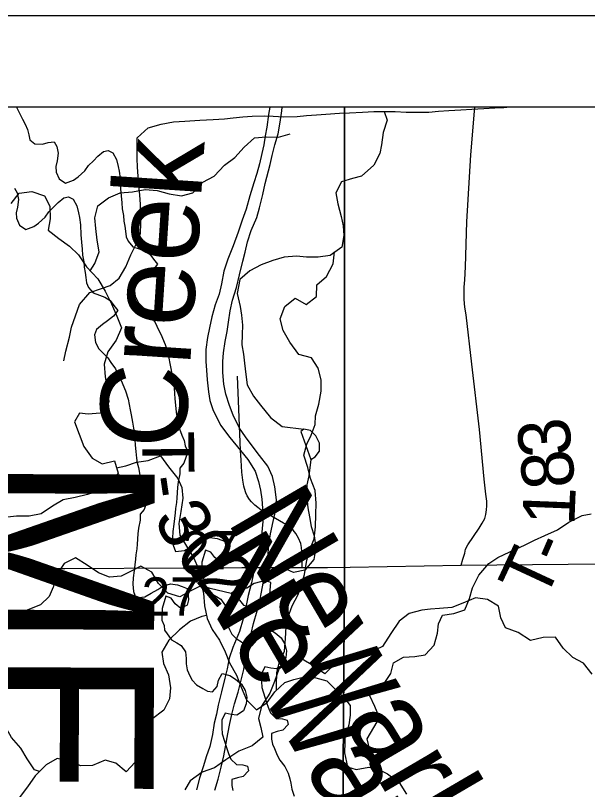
# Model space of a CAD drawing. Extents: x -21.1 to 50.3, y 0 to 22.1.
# Drawn here: x 6.171 to 6.795, y 20.155 to 21 of the extents above; entities that cross this region are included whole.
import ezdxf

# ---------------------------------------------------------------- set-up
doc = ezdxf.new("R2010")
doc.units = 0
for name, color, linetype in [('GM_X_County', 7, 'Continuous'), ('GM_X_County_Text', 7, 'Continuous'), ('GM_X_Minor_Lake', 7, 'Continuous'), ('GM_X_Minor_River', 7, 'Continuous'), ('GM_X_Minor_River_Text', 7, 'Continuous'), ('GM_X_Section_Text', 7, 'Continuous'), ('GM_X_State_Route', 7, 'Continuous'), ('GM_X_Township_Road', 7, 'Continuous'), ('GM_X_Township_Road_Text', 7, 'Continuous'), ('SH_Cut_Line', 7, 'Continuous'), ('SH_Data', 7, 'Continuous')]:
    doc.layers.add(name, color=color, linetype=linetype)

msp = doc.modelspace()

# ---------------------------------------------------------------- linework, layer by layer
at = {"layer": 'GM_X_County'}
msp.add_lwpolyline([(8.9, 14.74638), (8.9, 20.9), (2.1, 20.9), (2.1, 14.1), (8.89319, 14.1)], dxfattribs=at)
at = {"layer": 'GM_X_Minor_Lake'}
for points in [[(6.49289, 20.51509), (6.49782, 20.51812), (6.50237, 20.52419), (6.50238, 20.53291), (6.49821, 20.54088), (6.49253, 20.54694), (6.48533, 20.54808), (6.48191, 20.54581)], [(6.48191, 20.54581), (6.49289, 20.51509)], [(6.44922, 20.38083), (6.44354, 20.38272), (6.43785, 20.38158), (6.43103, 20.37969), (6.42307, 20.37475), (6.41662, 20.37399), (6.4098, 20.37134), (6.406, 20.36868), (6.40676, 20.36679), (6.41358, 20.36337), (6.41964, 20.35617), (6.42381, 20.35503), (6.4314, 20.35655), (6.43936, 20.35996), (6.44467, 20.36224), (6.4477, 20.36376)], [(6.4477, 20.36376), (6.44922, 20.38083)]]:
    msp.add_lwpolyline(points, dxfattribs=at)
at = {"layer": 'GM_X_Minor_River'}
for points in [[(6.17189, 20.9), (6.17446, 20.89495), (6.17831, 20.88661), (6.18138, 20.88131), (6.1837, 20.87563), (6.18526, 20.86955), (6.18643, 20.86424), (6.19178, 20.85971), (6.20016, 20.85938), (6.20624, 20.86131), (6.21271, 20.86211)], [(6.22342, 20.62276), (6.2257, 20.63338), (6.2295, 20.64855), (6.23178, 20.65955), (6.23596, 20.67207), (6.24051, 20.6842), (6.25189, 20.69748), (6.2644, 20.70203), (6.27389, 20.70506), (6.28374, 20.71303), (6.29095, 20.72555), (6.29665, 20.73844), (6.30348, 20.75247), (6.3069, 20.76233), (6.30728, 20.77258), (6.3069, 20.78395), (6.30691, 20.79343), (6.30616, 20.80405), (6.30541, 20.81391), (6.30465, 20.82453), (6.3039, 20.83439), (6.30353, 20.84387), (6.30354, 20.86625), (6.3153, 20.87725), (6.3297, 20.88142), (6.34297, 20.8837), (6.35548, 20.88446), (6.37178, 20.8856), (6.38619, 20.88636), (6.3987, 20.88712), (6.40818, 20.88826), (6.41879, 20.8894), (6.42903, 20.89016), (6.4423, 20.89054), (6.45177, 20.89016), (6.46352, 20.8894), (6.47793, 20.88978), (6.48816, 20.89092), (6.49916, 20.89168), (6.50939, 20.89206), (6.52418, 20.8932), (6.53517, 20.89358), (6.5492, 20.89434), (6.56171, 20.8951), (6.57308, 20.89511), (6.58483, 20.89511), (6.59696, 20.89435), (6.6216, 20.89435), (6.63222, 20.89549), (6.64359, 20.89625), (6.65648, 20.89701), (6.66861, 20.89777), (6.68188, 20.89853), (6.69363, 20.89929), (6.70348, 20.89967), (6.70676, 20.9)], [(6.44809, 20.9), (6.4468, 20.89182), (6.44476, 20.87817), (6.44315, 20.86869), (6.44153, 20.85883), (6.43953, 20.84935), (6.43676, 20.83798), (6.43399, 20.82737), (6.43085, 20.81715), (6.42653, 20.80314), (6.4222, 20.78836), (6.41791, 20.77663), (6.41359, 20.76338), (6.40813, 20.74862), (6.40228, 20.73387), (6.39797, 20.72061), (6.39555, 20.70696), (6.39277, 20.6956), (6.38848, 20.68386), (6.38493, 20.67098), (6.38253, 20.65885), (6.38014, 20.64824), (6.37849, 20.63534), (6.37835, 20.62205), (6.37902, 20.61254), (6.37967, 20.60228), (6.38143, 20.58897), (6.38285, 20.57946), (6.38616, 20.56955), (6.39434, 20.55275), (6.40445, 20.53897), (6.41607, 20.5248), (6.42432, 20.51522), (6.43216, 20.50222), (6.43584, 20.49117), (6.43802, 20.48165), (6.43944, 20.47176), (6.4401, 20.46188), (6.44074, 20.45085), (6.43988, 20.44023), (6.43902, 20.43074), (6.437, 20.41898), (6.43421, 20.40572), (6.43026, 20.39094), (6.42825, 20.38033), (6.42469, 20.36669), (6.4223, 20.35569), (6.41912, 20.34129), (6.41518, 20.32728), (6.40779, 20.30988), (6.40387, 20.29814), (6.40147, 20.28639), (6.39909, 20.27616), (6.39552, 20.26138), (6.39195, 20.24698), (6.38995, 20.23712), (6.38757, 20.22727), (6.38555, 20.21476), (6.38276, 20.20187), (6.37884, 20.19051), (6.37571, 20.18067), (6.37139, 20.16704), (6.36823, 20.15453)], [(6.38834, 20.15395), (6.39188, 20.16607), (6.39505, 20.17895), (6.39784, 20.19146), (6.39983, 20.20132), (6.40226, 20.21535), (6.40465, 20.22672), (6.40665, 20.23658), (6.40981, 20.24832), (6.41374, 20.26119), (6.41691, 20.27408), (6.41968, 20.28583), (6.42211, 20.30024), (6.42413, 20.31237), (6.42768, 20.32525), (6.43045, 20.33586), (6.43439, 20.34987), (6.43716, 20.36086), (6.43916, 20.37034), (6.44078, 20.3802), (6.44358, 20.39461), (6.446, 20.40788), (6.44728, 20.4223), (6.44892, 20.43406), (6.45172, 20.44733), (6.45449, 20.45869), (6.45538, 20.47122), (6.45363, 20.48529), (6.45109, 20.49671), (6.44589, 20.50778), (6.4369, 20.51965), (6.42903, 20.52999), (6.42154, 20.53994), (6.41519, 20.5495), (6.40812, 20.56363), (6.40405, 20.57392), (6.4, 20.5865), (6.39784, 20.59754), (6.39683, 20.61008), (6.39695, 20.62224), (6.39781, 20.63173), (6.39946, 20.64387), (6.40147, 20.65486), (6.40309, 20.6651), (6.40474, 20.67762), (6.40751, 20.68899), (6.41183, 20.703), (6.41501, 20.71664), (6.41858, 20.7318), (6.42134, 20.74165), (6.42373, 20.75264), (6.42766, 20.76514), (6.43388, 20.77951), (6.43702, 20.79011), (6.44059, 20.80451), (6.44299, 20.81665), (6.44852, 20.8371), (6.4509, 20.84696), (6.45367, 20.8587), (6.45722, 20.87082), (6.45962, 20.88333), (6.46127, 20.89585), (6.46179, 20.9)], [(6.57308, 20.89511), (6.57611, 20.88562), (6.57193, 20.87235), (6.57003, 20.8587), (6.56813, 20.84922), (6.56168, 20.8367), (6.5484, 20.82456), (6.53854, 20.82191), (6.52641, 20.81849), (6.52034, 20.80635), (6.52223, 20.79422), (6.52601, 20.78057), (6.52828, 20.77033), (6.52903, 20.75971), (6.52675, 20.74681), (6.51386, 20.73771), (6.50097, 20.73619), (6.48808, 20.73619), (6.47747, 20.73733), (6.46382, 20.73619), (6.45131, 20.73239), (6.43879, 20.72784), (6.42628, 20.72101), (6.41529, 20.71153), (6.41262, 20.69636), (6.41565, 20.68233), (6.41716, 20.67285), (6.41829, 20.66185), (6.4179, 20.65161), (6.41752, 20.64023), (6.41941, 20.62999), (6.42054, 20.62013), (6.42205, 20.608), (6.42356, 20.59662), (6.43038, 20.5841), (6.43796, 20.57462), (6.44894, 20.56097), (6.46183, 20.55111), (6.48533, 20.54808)], [(6.25213, 20.72115), (6.25709, 20.72899), (6.26202, 20.74193), (6.25972, 20.75447), (6.25817, 20.7674), (6.2574, 20.77919), (6.26042, 20.79213), (6.27221, 20.80089), (6.28475, 20.80623), (6.29845, 20.80739), (6.31214, 20.81007), (6.32508, 20.80895), (6.33841, 20.80516), (6.35173, 20.8029), (6.36428, 20.80634), (6.37492, 20.81814), (6.38746, 20.82462), (6.39886, 20.83643), (6.40988, 20.84481), (6.42014, 20.85624), (6.43154, 20.86652), (6.44409, 20.8673), (6.45779, 20.86694), (6.47034, 20.87075)], [(6.21271, 20.86211), (6.21578, 20.85681), (6.21734, 20.8496), (6.21625, 20.84123), (6.21476, 20.83515), (6.21518, 20.82907), (6.21826, 20.82149), (6.22514, 20.81697), (6.23388, 20.82005), (6.23918, 20.82388), (6.24638, 20.83038), (6.25016, 20.8361), (6.25584, 20.84145), (6.26038, 20.84642), (6.26682, 20.85139), (6.27176, 20.85256), (6.27673, 20.84992), (6.28095, 20.84273), (6.28252, 20.83514), (6.28369, 20.82983), (6.28488, 20.82186), (6.28532, 20.81084), (6.28612, 20.80287), (6.28655, 20.79527), (6.28697, 20.78882), (6.28853, 20.78161), (6.28894, 20.77553), (6.29012, 20.76984), (6.29053, 20.76452), (6.29132, 20.75845), (6.29363, 20.75352), (6.29862, 20.74747), (6.30548, 20.74523), (6.31158, 20.74298), (6.31732, 20.73922), (6.32115, 20.73392), (6.32575, 20.72825), (6.32084, 20.72214), (6.31439, 20.71717), (6.30871, 20.71296), (6.30226, 20.7076), (6.30001, 20.70189), (6.3012, 20.69354), (6.30505, 20.68634), (6.31462, 20.67652), (6.31808, 20.6716), (6.32306, 20.66479), (6.32653, 20.65683), (6.32922, 20.65191), (6.33386, 20.64054), (6.33695, 20.63143), (6.33892, 20.62005), (6.34009, 20.61436), (6.34166, 20.60639), (6.34284, 20.59994), (6.34364, 20.59348), (6.34405, 20.58702), (6.34446, 20.58133), (6.34526, 20.5745), (6.34607, 20.5669), (6.34686, 20.56197), (6.34803, 20.55703), (6.3496, 20.54869), (6.3523, 20.54186), (6.35461, 20.5358), (6.35579, 20.53011), (6.35887, 20.52366), (6.35437, 20.5111), (6.34984, 20.50576), (6.34987, 20.4993), (6.34802, 20.49055), (6.34729, 20.48447), (6.34659, 20.47307), (6.34624, 20.46813), (6.34513, 20.46166), (6.34478, 20.45672), (6.34333, 20.44456), (6.34223, 20.43658), (6.34189, 20.42936), (6.34269, 20.42138), (6.3454, 20.41456), (6.35491, 20.41575), (6.36212, 20.41959), (6.36933, 20.42381), (6.37464, 20.42726), (6.383, 20.42996), (6.39061, 20.42887), (6.39596, 20.427), (6.4013, 20.42474), (6.40248, 20.41753), (6.40289, 20.41222), (6.4014, 20.40651), (6.39419, 20.40305), (6.38807, 20.40796), (6.38385, 20.41401), (6.37812, 20.41626), (6.37401, 20.40294), (6.37367, 20.39572), (6.3737, 20.39002), (6.37602, 20.38434), (6.37643, 20.3794)], [(6.16942, 20.81159), (6.17249, 20.80629), (6.17406, 20.79908), (6.17296, 20.79072), (6.17147, 20.78463), (6.17189, 20.77855), (6.17497, 20.77097), (6.18185, 20.76645), (6.19059, 20.76954), (6.1959, 20.77337), (6.20309, 20.77987), (6.20687, 20.78558), (6.21255, 20.79093), (6.21709, 20.7959), (6.22353, 20.80087), (6.22847, 20.80204), (6.23344, 20.79941), (6.23767, 20.79221), (6.23923, 20.78463), (6.2404, 20.77931), (6.24159, 20.77134), (6.24203, 20.76033), (6.24284, 20.75235), (6.24326, 20.74476), (6.24368, 20.7383), (6.24524, 20.73109), (6.24565, 20.72502), (6.24683, 20.71932), (6.24724, 20.71401), (6.24803, 20.70793), (6.25035, 20.70301), (6.25533, 20.69696), (6.26219, 20.69472), (6.26829, 20.69247), (6.27403, 20.6887), (6.27786, 20.6834), (6.28246, 20.67773), (6.27755, 20.67163), (6.2711, 20.66665), (6.26542, 20.66244), (6.25898, 20.65709), (6.25673, 20.65138), (6.25791, 20.64302), (6.26176, 20.63583), (6.27133, 20.626), (6.27479, 20.62108), (6.27977, 20.61427), (6.28324, 20.60632), (6.28593, 20.60139), (6.29057, 20.59002), (6.29366, 20.58092), (6.29563, 20.56953), (6.2968, 20.56384), (6.29837, 20.55587), (6.29955, 20.54942), (6.30035, 20.54297), (6.30076, 20.53651), (6.30117, 20.53081), (6.30197, 20.52398), (6.30278, 20.51639), (6.30357, 20.51145), (6.30474, 20.50652), (6.30631, 20.49817), (6.30901, 20.49135), (6.31133, 20.48528), (6.3125, 20.47959), (6.31558, 20.47315), (6.31108, 20.46059), (6.30655, 20.45524), (6.30658, 20.44879), (6.30473, 20.44004), (6.304, 20.43396), (6.3033, 20.42255), (6.30295, 20.41761), (6.30185, 20.41115), (6.30149, 20.40621), (6.30004, 20.39404), (6.29894, 20.38606), (6.2986, 20.37884), (6.29941, 20.37086), (6.30211, 20.36404), (6.31162, 20.36523), (6.31883, 20.36907), (6.32604, 20.37329), (6.33135, 20.37674), (6.33971, 20.37945), (6.34733, 20.37835), (6.35267, 20.37648), (6.35801, 20.37423), (6.35919, 20.36702), (6.3596, 20.3617), (6.35811, 20.356), (6.3509, 20.35254), (6.34478, 20.35744), (6.34056, 20.3635), (6.33484, 20.36574), (6.33072, 20.35242), (6.33038, 20.34521), (6.33041, 20.33951), (6.33273, 20.33382), (6.33314, 20.32888)], [(6.16606, 20.79466), (6.17479, 20.80609), (6.18849, 20.80763), (6.20219, 20.80308), (6.2083, 20.79168), (6.20832, 20.77799), (6.20643, 20.76543), (6.21786, 20.75632), (6.22967, 20.74797), (6.23957, 20.73847), (6.24796, 20.72556), (6.26054, 20.71226), (6.26855, 20.69896), (6.27542, 20.68528), (6.28114, 20.67159), (6.28649, 20.65905), (6.28042, 20.64535), (6.27131, 20.63279), (6.26752, 20.61909), (6.26868, 20.6054), (6.27099, 20.59171), (6.27253, 20.57802), (6.26303, 20.56584), (6.2501, 20.56468), (6.24058, 20.56581), (6.23489, 20.55629), (6.24024, 20.54261), (6.2452, 20.52931), (6.25435, 20.51639), (6.26539, 20.51032), (6.27871, 20.51376), (6.28253, 20.50007), (6.27456, 20.48751), (6.26201, 20.48103), (6.24908, 20.47683), (6.23577, 20.47377), (6.22284, 20.47109), (6.21105, 20.46423), (6.19851, 20.45584), (6.18557, 20.45316), (6.17188, 20.45314), (6.15856, 20.4516)], [(6.45548, 20.2631), (6.45561, 20.26907), (6.45597, 20.28238), (6.45862, 20.29417), (6.46431, 20.30597), (6.46543, 20.31966), (6.46617, 20.33221), (6.46768, 20.3421), (6.4726, 20.35542), (6.47906, 20.3676), (6.48323, 20.37978), (6.48587, 20.38967), (6.48814, 20.40298), (6.49117, 20.41516), (6.49647, 20.42848), (6.49797, 20.44141), (6.49834, 20.4551), (6.4987, 20.46727), (6.49754, 20.48134), (6.49257, 20.49427), (6.48951, 20.50643), (6.48531, 20.51974), (6.48871, 20.53191), (6.49326, 20.54181), (6.49782, 20.55322), (6.49818, 20.56273), (6.50159, 20.57567), (6.50423, 20.58974), (6.50421, 20.60229), (6.50077, 20.61484), (6.49353, 20.62624), (6.47982, 20.62964), (6.46991, 20.64332), (6.46266, 20.65586), (6.4596, 20.66879), (6.46453, 20.68211), (6.47593, 20.69125), (6.48773, 20.68442), (6.49914, 20.69318), (6.4995, 20.70573), (6.51014, 20.71488), (6.51735, 20.72896), (6.51885, 20.74189)], [(6.28083, 20.50615), (6.29089, 20.50807), (6.30268, 20.51227), (6.31561, 20.51419), (6.32892, 20.51915), (6.33769, 20.50699), (6.34798, 20.49445), (6.35218, 20.48457), (6.35334, 20.47278), (6.35108, 20.45833), (6.34882, 20.44539), (6.34998, 20.43246), (6.35722, 20.4203), (6.36485, 20.40814), (6.3702, 20.3956), (6.3725, 20.38191), (6.37594, 20.36899), (6.37672, 20.3553), (6.37979, 20.34161), (6.38513, 20.32945), (6.39314, 20.31767), (6.39962, 20.30512), (6.40421, 20.29296), (6.41184, 20.27966), (6.4168, 20.26635), (6.42291, 20.25267), (6.43358, 20.24166), (6.44536, 20.24966), (6.45372, 20.26146), (6.46474, 20.27174), (6.47424, 20.2748), (6.48603, 20.27785), (6.49821, 20.27673), (6.51039, 20.27332), (6.53015, 20.25396)], [(6.49289, 20.51509), (6.49061, 20.49726), (6.48871, 20.4874), (6.48832, 20.47602), (6.48983, 20.46237), (6.49134, 20.45251), (6.49323, 20.44189), (6.49664, 20.43165), (6.49853, 20.41914), (6.49624, 20.40586), (6.48638, 20.3941), (6.47387, 20.39183), (6.46099, 20.39751), (6.44354, 20.38272)], [(6.56004, 20.17839), (6.56033, 20.1857), (6.55719, 20.19783), (6.55442, 20.20996), (6.56152, 20.22257), (6.56788, 20.23289), (6.56283, 20.24538), (6.55741, 20.25711), (6.5615, 20.26703), (6.57135, 20.26826), (6.58035, 20.28127), (6.58328, 20.29307), (6.59422, 20.29926), (6.60636, 20.30013), (6.61773, 20.30176), (6.6275, 20.31249), (6.63118, 20.32545), (6.63222, 20.33572), (6.63669, 20.34526), (6.64882, 20.34689), (6.66093, 20.35081), (6.66613, 20.3634), (6.66944, 20.37483), (6.67615, 20.38895), (6.68704, 20.40159), (6.69685, 20.40815), (6.71007, 20.41435), (6.72594, 20.42172), (6.7369, 20.42715), (6.74824, 20.43219), (6.76222, 20.4384), (6.77429, 20.4465), (6.78903, 20.45386), (6.79888, 20.45585)], [(6.406, 20.36868), (6.38326, 20.37437), (6.37379, 20.3774), (6.36203, 20.37171), (6.3499, 20.36526), (6.33701, 20.36905), (6.32678, 20.37967), (6.31959, 20.39219), (6.30746, 20.39863), (6.29684, 20.39332), (6.28585, 20.38763), (6.27334, 20.38649), (6.26121, 20.39142), (6.2487, 20.39976), (6.2362, 20.40772), (6.22368, 20.40165), (6.21496, 20.38838), (6.21192, 20.37587), (6.20736, 20.36562), (6.19788, 20.35652), (6.18423, 20.35083), (6.17437, 20.34628), (6.16451, 20.33831)], [(6.37643, 20.3794), (6.3841, 20.3688), (6.38983, 20.36542), (6.39479, 20.36241), (6.3994, 20.35559), (6.4002, 20.34838), (6.40024, 20.3423), (6.40141, 20.33585), (6.40411, 20.32941), (6.40681, 20.32448), (6.4114, 20.31957), (6.41828, 20.31543), (6.42362, 20.3128), (6.42895, 20.31207), (6.43387, 20.31779), (6.43536, 20.32464), (6.4395, 20.33188), (6.44789, 20.32965), (6.454, 20.32588), (6.4605, 20.32022), (6.46473, 20.31341), (6.46629, 20.3062), (6.46557, 20.29898), (6.46257, 20.29098), (6.45536, 20.28638), (6.44927, 20.28711), (6.44279, 20.28859), (6.43903, 20.28097), (6.43907, 20.27261), (6.43949, 20.26616), (6.44453, 20.24985), (6.44646, 20.24454), (6.44878, 20.23848), (6.45528, 20.23244), (6.46214, 20.23209), (6.4671, 20.2306), (6.46826, 20.22567), (6.46221, 20.21956), (6.45613, 20.218), (6.45005, 20.21607), (6.45008, 20.20961), (6.45126, 20.2043), (6.45318, 20.19937), (6.45627, 20.19217), (6.45897, 20.18687), (6.46472, 20.17968), (6.46818, 20.17248), (6.47012, 20.16642), (6.47129, 20.16148), (6.47209, 20.15503), (6.47479, 20.14745)], [(6.79982, 20.28074), (6.79035, 20.29288), (6.77898, 20.29894), (6.76837, 20.30918), (6.76004, 20.32094), (6.74639, 20.32056), (6.73274, 20.31752), (6.7191, 20.32624), (6.70545, 20.33117), (6.70015, 20.34217), (6.69789, 20.35507), (6.68576, 20.36227), (6.67249, 20.36417), (6.65884, 20.35809), (6.64671, 20.35354), (6.63344, 20.3524), (6.62358, 20.35164), (6.61411, 20.3505), (6.60008, 20.34709), (6.58946, 20.33874), (6.58036, 20.32509), (6.57125, 20.31105), (6.55646, 20.30385)], [(6.3791, 20.34467), (6.37408, 20.3435), (6.36153, 20.33854), (6.34975, 20.32902), (6.33796, 20.31797), (6.33038, 20.30465), (6.33229, 20.29248), (6.33764, 20.27994), (6.33994, 20.26587), (6.33882, 20.2537), (6.33237, 20.24152), (6.31906, 20.23123), (6.30881, 20.22133), (6.3054, 20.2084), (6.30352, 20.19584), (6.30125, 20.18443), (6.29137, 20.17415), (6.28032, 20.18364), (6.26852, 20.18667), (6.25483, 20.18095), (6.2419, 20.18055), (6.22971, 20.18548), (6.21601, 20.1885), (6.20423, 20.18164), (6.19207, 20.16983), (6.18371, 20.15765), (6.1746, 20.14547)], [(6.19668, 20.17431), (6.1913, 20.1763), (6.18329, 20.18808), (6.17642, 20.19986), (6.16614, 20.21164), (6.15927, 20.22379), (6.14822, 20.23329), (6.13603, 20.24506), (6.12384, 20.25455), (6.11127, 20.26367), (6.09946, 20.27392), (6.08841, 20.28607), (6.07811, 20.29861), (6.06669, 20.30848), (6.05488, 20.31607), (6.04117, 20.32594), (6.02822, 20.33315)], [(6.33314, 20.32888), (6.34081, 20.31829), (6.34654, 20.3149), (6.3515, 20.31189), (6.35611, 20.30508), (6.35691, 20.29786), (6.35695, 20.29179), (6.35813, 20.28533), (6.36083, 20.27889), (6.36352, 20.27397), (6.36811, 20.26905), (6.37499, 20.26491), (6.38033, 20.26228), (6.38567, 20.26155), (6.39058, 20.26728), (6.39207, 20.27412), (6.39621, 20.28137), (6.4046, 20.27913), (6.41071, 20.27537), (6.41721, 20.26971), (6.42144, 20.26289), (6.423, 20.25568), (6.42228, 20.24846), (6.41928, 20.24047), (6.41207, 20.23586), (6.40598, 20.23659), (6.3995, 20.23808), (6.39574, 20.23046), (6.39578, 20.2221), (6.3962, 20.21564), (6.40124, 20.19934), (6.40317, 20.19403), (6.40549, 20.18796), (6.41199, 20.18192), (6.41885, 20.18158), (6.42381, 20.18009), (6.42498, 20.17515), (6.41892, 20.16904), (6.41284, 20.16749), (6.40676, 20.16556), (6.4068, 20.1591), (6.40797, 20.15379)], [(6.55646, 20.30385), (6.54699, 20.30309), (6.53334, 20.30119), (6.52083, 20.2936), (6.50831, 20.28109), (6.49504, 20.29019), (6.4833, 20.29701), (6.47117, 20.29587), (6.4579, 20.28601), (6.45334, 20.27273), (6.44802, 20.25984), (6.43892, 20.24581), (6.43588, 20.23215), (6.43853, 20.22229), (6.44042, 20.21205), (6.42904, 20.20257), (6.41425, 20.1965), (6.40022, 20.18702), (6.38771, 20.17829), (6.37444, 20.17374), (6.36116, 20.16426), (6.35547, 20.15439)], [(6.53015, 20.25396), (6.53588, 20.24665), (6.53597, 20.23601), (6.53455, 20.22536), (6.53006, 20.21062), (6.53006, 20.20597), (6.52976, 20.19492), (6.53307, 20.17936), (6.54258, 20.17641), (6.55621, 20.1792), (6.56648, 20.17702), (6.57677, 20.1718), (6.58938, 20.16242), (6.59746, 20.14958)]]:
    msp.add_lwpolyline(points, dxfattribs=at)
at = {"layer": 'GM_X_State_Route'}
for points in [[(6.52955, 20.9), (2.1, 20.9), (2.1, 17.74017), (2.42851, 17.74626), (2.73209, 17.75291), (3.03298, 17.75833), (3.3026, 17.76263), (3.44154, 17.76826), (3.94025, 17.77171), (5.33072, 17.79178), (6.52196, 17.81036), (6.52225, 18.35692), (6.52255, 18.97782), (6.52273, 19.34666), (6.52977, 20.39859)], [(8.9, 17.84218), (8.9, 20.9), (6.52955, 20.9), (6.52977, 20.39859), (6.52273, 19.34666), (6.52255, 18.97782), (6.52225, 18.35692), (6.52196, 17.81036), (6.66406, 17.81203), (6.69997, 17.81193), (6.90933, 17.81425), (7.58368, 17.81946), (7.86638, 17.82395), (8.25757, 17.83124)]]:
    msp.add_lwpolyline(points, close=True, dxfattribs=at)
for points in [[(5.80464, 20.39478), (5.84123, 20.39505), (5.85978, 20.39492), (5.87436, 20.39505), (5.92129, 20.39478), (5.95562, 20.39492), (6.01208, 20.39505), (6.03462, 20.39518), (6.05384, 20.39532), (6.11296, 20.39558), (6.15047, 20.39571), (6.20283, 20.39597), (6.22444, 20.39611), (6.35375, 20.39675)], [(6.35375, 20.39675), (6.38483, 20.39691), (6.41757, 20.39704), (6.42357, 20.39705)], [(6.42357, 20.39705), (6.48357, 20.39717), (6.51101, 20.3973), (6.5358, 20.39765)], [(6.5358, 20.39765), (6.65697, 20.3996), (6.96801, 20.40274), (7.42177, 20.40498)]]:
    msp.add_lwpolyline(points, dxfattribs=at)
at = {"layer": 'GM_X_Township_Road'}
for points in [[(6.65697, 20.3996), (6.65892, 20.40616), (6.66083, 20.41268), (6.66178, 20.41713), (6.66417, 20.42206), (6.67657, 20.44004), (6.68007, 20.44561), (6.68278, 20.45086), (6.68405, 20.45515), (6.68453, 20.46024), (6.68485, 20.46454), (6.68485, 20.46963), (6.68373, 20.4771), (6.68198, 20.4938), (6.67689, 20.54789), (6.66878, 20.61931), (6.66242, 20.67292), (6.66114, 20.68151), (6.66035, 20.68978), (6.66019, 20.69662), (6.66035, 20.70346), (6.66114, 20.71125), (6.66178, 20.72541), (6.66308, 20.7747), (6.66749, 20.84791), (6.672, 20.9)], [(6.48357, 20.39717), (6.48339, 20.40538), (6.48318, 20.41466), (6.48278, 20.41891), (6.48198, 20.42328), (6.4796, 20.42925), (6.47655, 20.43442), (6.47363, 20.43802), (6.46926, 20.44144), (6.46462, 20.44468), (6.46316, 20.44555), (6.4389, 20.45986), (6.43493, 20.46252), (6.43175, 20.46517), (6.42804, 20.46875), (6.42592, 20.4714), (6.42339, 20.47551), (6.42207, 20.47869), (6.42048, 20.48346), (6.41987, 20.48607), (6.41862, 20.4926), (6.4177, 20.50135), (6.4169, 20.51448), (6.41624, 20.52481), (6.41292, 20.6062)]]:
    msp.add_lwpolyline(points, dxfattribs=at)
at = {"layer": 'SH_Cut_Line'}
for points in [[(6.52955, 20.9), (2.1, 20.9), (2.1, 14.1), (6.50995, 14.1), (6.5113, 14.24348), (6.51114, 14.29418), (6.513, 14.41466), (6.51283, 14.60317), (6.5142, 14.9441), (6.51464, 15.03489), (6.514, 15.09364), (6.51465, 15.30312), (6.51595, 15.49226), (6.51982, 16.08256), (6.52123, 16.24517), (6.52315, 16.46813), (6.52222, 16.85672), (6.52013, 17.69645), (6.52053, 17.72081), (6.52196, 17.81036), (6.52225, 18.35692), (6.52255, 18.97782), (6.52273, 19.34666), (6.52977, 20.39859)], [(6.50995, 14.1), (8.9, 14.1), (8.9, 20.9), (6.52955, 20.9), (6.52977, 20.39859), (6.52273, 19.34666), (6.52255, 18.97782), (6.52225, 18.35692), (6.52196, 17.81036), (6.52053, 17.72081), (6.52013, 17.69645), (6.52222, 16.85672), (6.52315, 16.46813), (6.52123, 16.24517), (6.51982, 16.08256), (6.51595, 15.49226), (6.51465, 15.30312), (6.514, 15.09364), (6.51464, 15.03489), (6.5142, 14.9441), (6.51283, 14.60317), (6.513, 14.41466), (6.51114, 14.29418), (6.5113, 14.24348)]]:
    msp.add_lwpolyline(points, close=True, dxfattribs=at)
at = {"layer": 'SH_Data'}
msp.add_line((2, 21), (9, 21), dxfattribs=at)

# ---------------------------------------------------------------- texts
at = {"layer": 'GM_X_County_Text'}
msp.add_text('MEDINA COUNTY', height=0.1893939, rotation=269.77943, dxfattribs=at).set_placement((6.13328, 20.52009))
at = {"layer": 'GM_X_Minor_River_Text'}
for s, height, rotation, p in [('Creek', 0.094734, 86.27482, (6.35515, 20.52481)), ('Newark', 0.094727, 300.3163, (6.40033, 20.44898)), ('Newark', 0.094727, 300.3163, (6.35704, 20.39847))]:
    msp.add_text(s, height=height, rotation=rotation, dxfattribs=at).set_placement(p)
at = {"layer": 'GM_X_Section_Text'}
for p in [(6.35151, 20.39504), (6.30822, 20.34453)]:
    msp.add_text('27', height=0.041856, rotation=0.00001, dxfattribs=at).set_placement(p)
at = {"layer": 'GM_X_Township_Road_Text'}
for s, rotation, p in [('3', 95.49881, (6.77805, 20.52067)), ('T', 270.61285, (6.30872, 20.54584)), ('8', 95.74247, (6.78154, 20.48591)), ('-', 278.43028, (6.30985, 20.49492)), ('1', 87.73101, (6.78042, 20.44229)), ('3', 299.09205, (6.32041, 20.4508)), ('0', 308.8103, (6.34329, 20.41151)), ('T', 65.05274, (6.74753, 20.35864)), ('-', 66.69255, (6.76618, 20.3988)), ('2', 310.10139, (6.36611, 20.38316))]:
    msp.add_text(s, height=0.05682, rotation=rotation, dxfattribs=at).set_placement(p)

doc.saveas('drawing.dxf')
